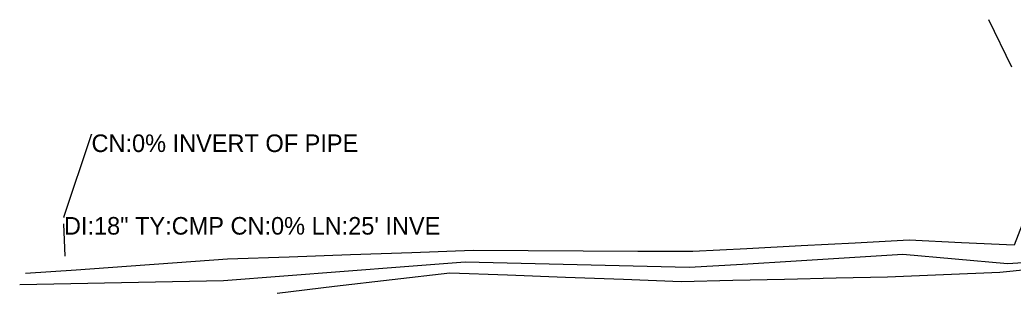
# Model space of a CAD drawing. Extents: x 1804576 to 1805329, y 515859 to 519427.
# Drawn here: x 1804578.3 to 1804860.5, y 517731.6 to 517808.2 of the extents above; entities that cross this region are included whole.
import ezdxf

# ---------------------------------------------------------------- set-up
doc = ezdxf.new("R2010")
doc.units = 0
for name, color, linetype in [('S_DITCHLINE', 7, 'Continuous'), ('S_DRG_PT_SYM', 7, 'Continuous'), ('S_SIDE_DRAIN', 7, 'Continuous'), ('S_SIDE_DRAIN_ANNOT', 7, 'Continuous'), ('S_STREAM', 7, 'Continuous')]:
    doc.layers.add(name, color=color, linetype=linetype)

msp = doc.modelspace()

# ---------------------------------------------------------------- linework, layer by layer
at = {"layer": 'S_DITCHLINE'}
for points in [[(1804860.18, 517794.77), (1804853.65, 517808.23)], [(1804590.7, 517750.22), (1804591.12, 517741)]]:
    msp.add_lwpolyline(points, dxfattribs=at)
at = {"layer": 'S_DRG_PT_SYM'}
for points in [[(1804598.7, 517775.62), (1804598.7, 517775.67), (1804598.7, 517775.62), (1804598.65, 517775.62), (1804598.7, 517775.62), (1804598.7, 517775.57), (1804598.7, 517775.62), (1804598.75, 517775.62)], [(1804590.86, 517752.13), (1804590.86, 517752.18), (1804590.86, 517752.13), (1804590.81, 517752.13), (1804590.86, 517752.13), (1804590.86, 517752.08), (1804590.86, 517752.13), (1804590.91, 517752.13)]]:
    msp.add_lwpolyline(points, dxfattribs=at)
at = {"layer": 'S_SIDE_DRAIN'}
msp.add_line((1804590.86, 517752.13), (1804598.7, 517775.62), dxfattribs=at)
at = {"layer": 'S_STREAM'}
for points in [[(1804891.18, 517743.82), (1804877.94, 517742.32), (1804864.7, 517740.81), (1804864.65, 517749.6), (1804863.08, 517749.98), (1804860.8, 517744.12), (1804845.91, 517744.83), (1804831.02, 517745.55), (1804815.66, 517744.74), (1804800.29, 517743.92), (1804784.93, 517743.11), (1804769.56, 517742.3), (1804753.95, 517742.37), (1804738.34, 517742.44), (1804722.73, 517742.52), (1804707.12, 517742.59), (1804689.69, 517741.98), (1804672.25, 517741.37), (1804654.82, 517740.76), (1804637.38, 517740.15), (1804623.03, 517739.12), (1804608.68, 517738.09), (1804594.32, 517737.06), (1804579.97, 517736.03)], [(1804875.1, 517739.9), (1804858.96, 517738.85), (1804844.1, 517740.14), (1804829.24, 517741.44), (1804814.06, 517740.52), (1804798.87, 517739.59), (1804783.69, 517738.67), (1804768.5, 517737.75), (1804752.58, 517738.13), (1804736.66, 517738.51), (1804720.74, 517738.9), (1804704.82, 517739.28), (1804687.66, 517737.95), (1804670.49, 517736.63), (1804653.33, 517735.3), (1804636.16, 517733.98), (1804621.71, 517733.7), (1804607.25, 517733.42), (1804592.8, 517733.14), (1804578.34, 517732.86)], [(1804984.11, 517731.52), (1804965.43, 517732.59), (1804950.73, 517731.88), (1804936.03, 517731.18), (1804912.17, 517732.34), (1804890.54, 517739.69), (1804873.63, 517738.04), (1804856.73, 517736.4), (1804840.8, 517735.72), (1804824.87, 517735.03), (1804810.22, 517734.71), (1804795.57, 517734.39), (1804780.92, 517734.07), (1804766.27, 517733.74), (1804749.82, 517734.36), (1804733.38, 517734.97), (1804716.93, 517735.58), (1804700.49, 517736.2), (1804684.14, 517734.26), (1804667.78, 517732.33), (1804651.43, 517730.4)]]:
    msp.add_lwpolyline(points, dxfattribs=at)

# ---------------------------------------------------------------- texts
at = {"layer": 'S_SIDE_DRAIN_ANNOT'}
for s, p in [('CN:0% INVERT OF PIPE', (1804598.7, 517770.62)), ('DI:18" TY:CMP CN:0% LN:25\' INVE', (1804590.86, 517747.13))]:
    msp.add_text(s, height=5, dxfattribs=at).set_placement(p)

doc.saveas('drawing.dxf')
